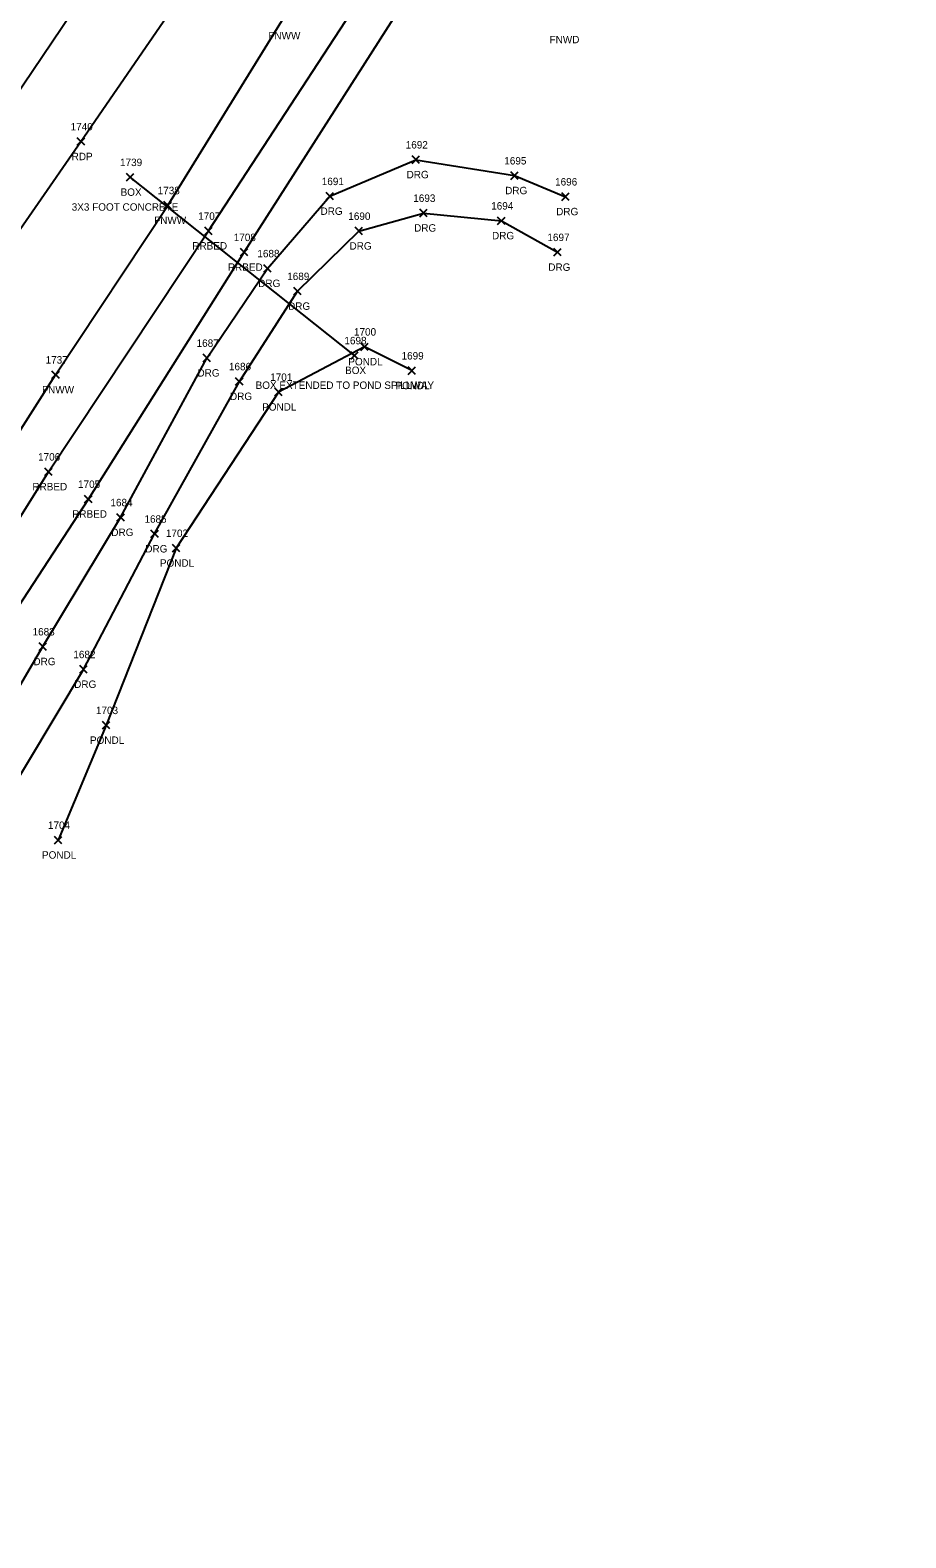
# Model space of a CAD drawing. Extents: x 1508122 to 1515053, y 865012 to 875267.
# Drawn here: x 1511388.1 to 1511623.7, y 869697.2 to 870102.7 of the extents above; entities that cross this region are included whole.
import ezdxf

# ---------------------------------------------------------------- set-up
doc = ezdxf.new("R2010")
doc.units = 0
for name, color, linetype in [('D_A', 7, 'Continuous'), ('D_C', 7, 'Continuous'), ('D_I', 7, 'Continuous'), ('D_TIC', 7, 'Continuous'), ('DDEFAULT', 7, 'Continuous'), ('L_A', 7, 'Continuous'), ('L_I', 7, 'Continuous'), ('L_TIC', 7, 'Continuous'), ('LAWE', 7, 'Continuous'), ('LFNC', 7, 'Continuous'), ('P_A', 7, 'Continuous'), ('P_I', 7, 'Continuous'), ('P_TIC', 7, 'Continuous'), ('PET', 7, 'Continuous'), ('R_A', 7, 'Continuous'), ('R_I', 7, 'Continuous'), ('R_TIC', 7, 'Continuous'), ('RDG', 7, 'Continuous'), ('RRB', 7, 'Continuous')]:
    doc.layers.add(name, color=color, linetype=linetype)

msp = doc.modelspace()

# ---------------------------------------------------------------- linework, layer by layer
at = {"layer": 'D_TIC'}
for points in [[(1511414.01, 870062.1), (1511416.01, 870064.1)], [(1511416.01, 870062.1), (1511414.01, 870064.1)], [(1511474.41, 870014.17), (1511476.41, 870016.17)], [(1511476.41, 870014.17), (1511474.41, 870016.17)]]:
    msp.add_lwpolyline(points, dxfattribs=at)
at = {"layer": 'DDEFAULT'}
msp.add_lwpolyline([(1511475.41, 870015.17), (1511415.01, 870063.1)], dxfattribs=at)
at = {"layer": 'L_TIC'}
for points in [[(1511424.13, 870054.54), (1511426.13, 870056.54)], [(1511426.13, 870054.54), (1511424.13, 870056.54)], [(1511477.1, 870016.51), (1511479.1, 870018.51)], [(1511479.1, 870016.51), (1511477.1, 870018.51)], [(1511393.98, 870008.98), (1511395.98, 870010.98)], [(1511395.98, 870008.98), (1511393.98, 870010.98)], [(1511489.79, 870010.08), (1511491.79, 870012.08)], [(1511491.79, 870010.08), (1511489.79, 870012.08)], [(1511453.92, 870004.33), (1511455.92, 870006.33)], [(1511455.92, 870004.33), (1511453.92, 870006.33)], [(1511426.42, 869962.35), (1511428.42, 869964.35)], [(1511428.42, 869962.35), (1511426.42, 869964.35)], [(1511407.6, 869914.71), (1511409.6, 869916.71)], [(1511409.6, 869914.71), (1511407.6, 869916.71)], [(1511394.69, 869883.83), (1511396.69, 869885.83)], [(1511396.69, 869883.83), (1511394.69, 869885.83)]]:
    msp.add_lwpolyline(points, dxfattribs=at)
at = {"layer": 'LAWE'}
msp.add_lwpolyline([(1511490.79, 870011.08), (1511478.1, 870017.51), (1511454.92, 870005.33), (1511427.42, 869963.35), (1511408.6, 869915.71), (1511395.69, 869884.83)], dxfattribs=at)
at = {"layer": 'LFNC'}
msp.add_lwpolyline([(1511290.91, 869849.18), (1511327.8, 869904.4), (1511394.98, 870009.98), (1511425.13, 870055.54), (1511455.87, 870105.19), (1511491.53, 870158.85), (1511535.01, 870223.89), (1511575.2, 870287.48), (1511608.77, 870338.28), (1511623.7, 870361.63)], dxfattribs=at)
at = {"layer": 'P_TIC'}
for points in [[(1511400.8, 870071.69), (1511402.8, 870073.69)], [(1511402.8, 870071.69), (1511400.8, 870073.69)]]:
    msp.add_lwpolyline(points, dxfattribs=at)
at = {"layer": 'PET'}
for points in [[(1510904.69, 869375.99), (1510944.1, 869457.65), (1510981.65, 869532.24), (1511024.08, 869604.47), (1511042.96, 869631.7), (1511093.88, 869696.57), (1511130.92, 869743.2), (1511165.56, 869789.59), (1511207.17, 869847.2), (1511226.31, 869876.38), (1511258, 869920.32), (1511287.1, 869956.26), (1511314.02, 869991.4), (1511347.57, 870034.24), (1511383.61, 870084.12), (1511412.26, 870126.56)], [(1510922.16, 869361.87), (1510963.34, 869449.46), (1511001.23, 869521.95), (1511042, 869590.98), (1511060.37, 869618.22), (1511110.19, 869682.89), (1511147.27, 869729.24), (1511182.11, 869775.48), (1511226.38, 869838.36), (1511244.52, 869863.34), (1511275.64, 869907.23), (1511304.66, 869942.55), (1511331.68, 869978), (1511364.79, 870019.42), (1511401.8, 870072.69), (1511429.85, 870113.63)]]:
    msp.add_lwpolyline(points, dxfattribs=at)
at = {"layer": 'R_TIC'}
for points in [[(1511490.9, 870066.82), (1511492.9, 870068.82)], [(1511492.9, 870066.82), (1511490.9, 870068.82)], [(1511517.42, 870062.53), (1511519.42, 870064.53)], [(1511519.42, 870062.53), (1511517.42, 870064.53)], [(1511467.75, 870056.98), (1511469.75, 870058.98)], [(1511469.75, 870056.98), (1511467.75, 870058.98)], [(1511531.14, 870056.87), (1511533.14, 870058.87)], [(1511533.14, 870056.87), (1511531.14, 870058.87)], [(1511492.93, 870052.47), (1511494.93, 870054.47)], [(1511494.93, 870052.47), (1511492.93, 870054.47)], [(1511513.89, 870050.4), (1511515.89, 870052.4)], [(1511515.89, 870050.4), (1511513.89, 870052.4)], [(1511435.1, 870047.65), (1511437.1, 870049.65)], [(1511437.1, 870047.65), (1511435.1, 870049.65)], [(1511475.55, 870047.63), (1511477.55, 870049.63)], [(1511477.55, 870047.63), (1511475.55, 870049.63)], [(1511444.67, 870041.93), (1511446.67, 870043.93)], [(1511446.67, 870041.93), (1511444.67, 870043.93)], [(1511529.02, 870041.93), (1511531.02, 870043.93)], [(1511531.02, 870041.93), (1511529.02, 870043.93)], [(1511451, 870037.57), (1511453, 870039.57)], [(1511453, 870037.57), (1511451, 870039.57)], [(1511459.03, 870031.44), (1511461.03, 870033.44)], [(1511461.03, 870031.44), (1511459.03, 870033.44)], [(1511434.65, 870013.48), (1511436.65, 870015.48)], [(1511436.65, 870013.48), (1511434.65, 870015.48)], [(1511443.4, 870007.19), (1511445.4, 870009.19)], [(1511445.4, 870007.19), (1511443.4, 870009.19)], [(1511392.09, 869982.89), (1511394.09, 869984.89)], [(1511394.09, 869982.89), (1511392.09, 869984.89)], [(1511402.78, 869975.54), (1511404.78, 869977.54)], [(1511404.78, 869975.54), (1511402.78, 869977.54)], [(1511411.47, 869970.61), (1511413.47, 869972.61)], [(1511413.47, 869970.61), (1511411.47, 869972.61)], [(1511420.62, 869966.18), (1511422.62, 869968.18)], [(1511422.62, 869966.18), (1511420.62, 869968.18)], [(1511390.52, 869935.86), (1511392.52, 869937.86)], [(1511392.52, 869935.86), (1511390.52, 869937.86)], [(1511401.49, 869929.75), (1511403.49, 869931.75)], [(1511403.49, 869929.75), (1511401.49, 869931.75)]]:
    msp.add_lwpolyline(points, dxfattribs=at)
at = {"layer": 'RDG'}
for points in [[(1511339.74, 869858.39), (1511370.12, 869900.42), (1511391.52, 869936.86), (1511412.47, 869971.61), (1511435.65, 870014.48), (1511452, 870038.57), (1511468.75, 870057.98), (1511491.9, 870067.82), (1511518.42, 870063.53), (1511532.14, 870057.87)], [(1511336.06, 869774.94), (1511325.59, 869785.69), (1511323.6, 869811.5), (1511351.89, 869857.7), (1511379.8, 869892.94), (1511402.49, 869930.75), (1511421.62, 869967.18), (1511444.4, 870008.19), (1511460.03, 870032.44), (1511476.55, 870048.63), (1511493.93, 870053.47), (1511514.89, 870051.4), (1511530.02, 870042.93)]]:
    msp.add_lwpolyline(points, dxfattribs=at)
at = {"layer": 'RRB'}
for points in [[(1510567.62, 868706.56), (1510590.3, 868741.33), (1510641.58, 868821.14), (1510694.12, 868904.03), (1510737.34, 868971.49), (1510810.55, 869083.19), (1510862.56, 869162.99), (1510923.65, 869257.51), (1510962.65, 869316.48), (1511003.03, 869380.52), (1511033.75, 869429.1), (1511076.21, 869490.94), (1511122.4, 869564.68), (1511156.76, 869618.82), (1511179.37, 869653.25), (1511213.93, 869708.42), (1511264.74, 869787.25), (1511286.05, 869815.23), (1511349.66, 869914.55), (1511393.09, 869983.89), (1511436.1, 870048.65), (1511490.68, 870132.35)], [(1510600.6, 868735.49), (1510651.55, 868814.96), (1510704.78, 868897.68), (1510748.11, 868964.85), (1510821.21, 869076.32), (1510873.49, 869156.69), (1510934.14, 869250.38), (1510973.56, 869310.54), (1511014.14, 869373.22), (1511046.88, 869423.36), (1511086.93, 869485.24), (1511132.78, 869556.33), (1511168.28, 869611.72), (1511189.07, 869644.73), (1511224.88, 869702.41), (1511269.99, 869771.64), (1511301.83, 869821.13), (1511359.57, 869908.74), (1511403.78, 869976.54), (1511445.67, 870042.93), (1511499.01, 870126.5)]]:
    msp.add_lwpolyline(points, dxfattribs=at)

# ---------------------------------------------------------------- texts
at = {"layer": 'D_A'}
for p in [(1511412.46, 870058.1), (1511472.85, 870010.17)]:
    msp.add_text('BOX', height=2, dxfattribs=at).set_placement(p)
at = {"layer": 'D_C'}
for s, p in [('3X3 FOOT CONCRETE', (1511399.31, 870054.1)), ('BOX EXTENDED TO POND SPILLWAY', (1511448.78, 870006.17))]:
    msp.add_text(s, height=2, dxfattribs=at).set_placement(p)
at = {"layer": 'D_I'}
for s, p in [('1739', (1511412.31, 870066.1)), ('1698', (1511472.67, 870018.17))]:
    msp.add_text(s, height=2, dxfattribs=at).set_placement(p)
at = {"layer": 'L_A'}
for s, p in [('FNWW', (1511452.21, 870100.19)), ('FNWD', (1511527.86, 870099.13)), ('FNWW', (1511421.48, 870050.54)), ('PONDL', (1511473.72, 870012.51)), ('FNWW', (1511391.33, 870004.98)), ('PONDL', (1511486.41, 870006.08)), ('PONDL', (1511450.54, 870000.33)), ('PONDL', (1511423.04, 869958.35)), ('PONDL', (1511404.22, 869910.71)), ('PONDL', (1511391.32, 869879.83))]:
    msp.add_text(s, height=2, dxfattribs=at).set_placement(p)
at = {"layer": 'L_I'}
for s, p in [('1738', (1511422.44, 870058.54)), ('1700', (1511475.24, 870020.51)), ('1737', (1511392.29, 870012.98)), ('1699', (1511488.04, 870014.08)), ('1701', (1511452.71, 870008.33)), ('1702', (1511424.65, 869966.35)), ('1703', (1511405.83, 869918.71)), ('1704', (1511392.92, 869887.83))]:
    msp.add_text(s, height=2, dxfattribs=at).set_placement(p)
at = {"layer": 'P_A'}
msp.add_text('RDP', height=2, dxfattribs=at).set_placement((1511399.29, 870067.69))
at = {"layer": 'P_I'}
msp.add_text('1740', height=2, dxfattribs=at).set_placement((1511399.02, 870075.69))
at = {"layer": 'R_A'}
for s, p in [('DRG', (1511489.39, 870062.82)), ('DRG', (1511515.91, 870058.53)), ('DRG', (1511466.24, 870052.98)), ('DRG', (1511529.63, 870052.87)), ('DRG', (1511491.42, 870048.47)), ('DRG', (1511512.38, 870046.4)), ('RRBED', (1511431.75, 870043.65)), ('DRG', (1511474.04, 870043.63)), ('RRBED', (1511441.32, 870037.93)), ('DRG', (1511527.51, 870037.93)), ('DRG', (1511449.48, 870033.57)), ('DRG', (1511457.52, 870027.44)), ('DRG', (1511433.14, 870009.48)), ('DRG', (1511441.89, 870003.19)), ('RRBED', (1511388.73, 869978.89)), ('RRBED', (1511399.43, 869971.54)), ('DRG', (1511409.96, 869966.61)), ('DRG', (1511419.11, 869962.18)), ('DRG', (1511389.01, 869931.86)), ('DRG', (1511399.97, 869925.75))]:
    msp.add_text(s, height=2, dxfattribs=at).set_placement(p)
at = {"layer": 'R_I'}
for s, p in [('1692', (1511489.16, 870070.82)), ('1695', (1511515.68, 870066.53)), ('1691', (1511466.58, 870060.98)), ('1696', (1511529.34, 870060.87)), ('1693', (1511491.19, 870056.47)), ('1694', (1511512.15, 870054.4)), ('1707', (1511433.33, 870051.65)), ('1690', (1511473.72, 870051.63)), ('1708', (1511442.9, 870045.93)), ('1697', (1511527.28, 870045.93)), ('1688', (1511449.26, 870041.57)), ('1689', (1511457.28, 870035.44)), ('1687', (1511432.91, 870017.48)), ('1686', (1511441.61, 870011.19)), ('1706', (1511390.26, 869986.89)), ('1705', (1511401.01, 869979.54)), ('1684', (1511409.73, 869974.61)), ('1685', (1511418.88, 869970.18)), ('1683', (1511388.78, 869939.86)), ('1682', (1511399.75, 869933.75))]:
    msp.add_text(s, height=2, dxfattribs=at).set_placement(p)

doc.saveas('drawing.dxf')
